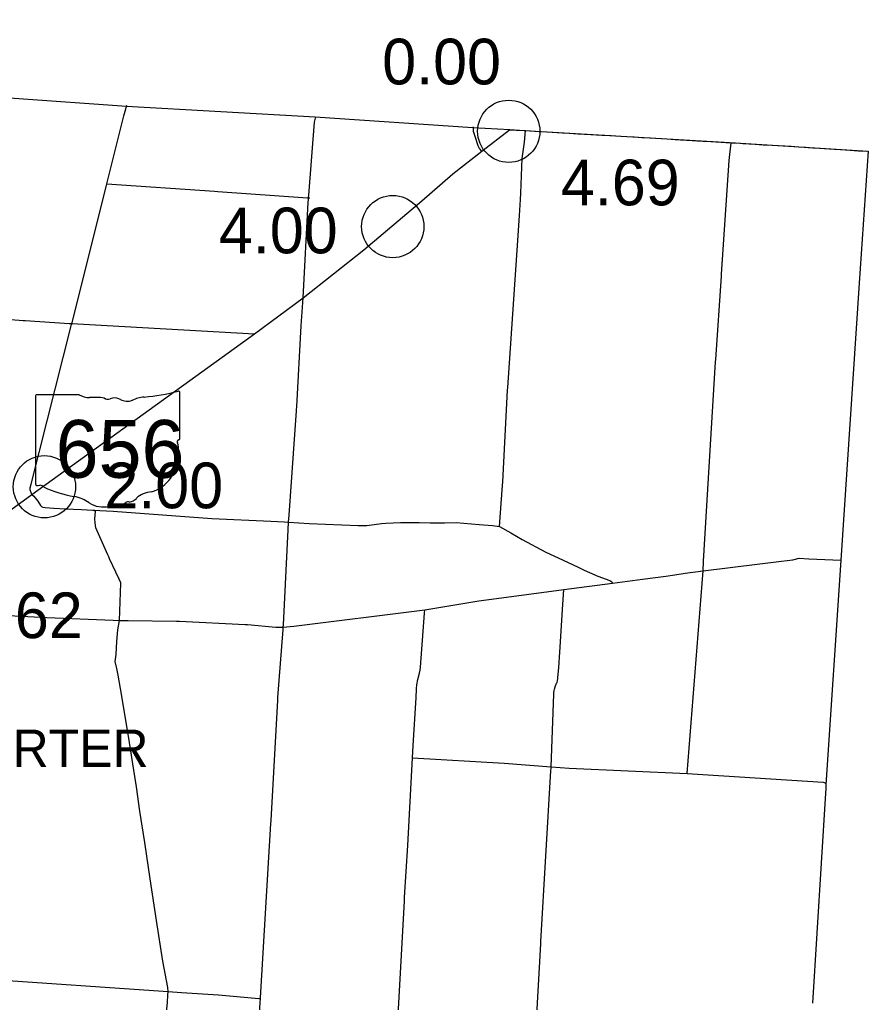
# Model space of a CAD drawing. Extents: x 1597222 to 1925846, y 496284 to 911751.
# Drawn here: x 1879776 to 1900207, y 835395 to 859080 of the extents above; entities that cross this region are included whole.
import ezdxf

# ---------------------------------------------------------------- set-up
doc = ezdxf.new("R2010")
doc.units = 0
for name, color, linetype in [('Default', 7, 'Continuous'), ('GM_X_County', 7, 'Continuous'), ('GM_X_County_Road', 7, 'Continuous'), ('GM_X_State_Route', 7, 'Continuous'), ('GM_X_State_Shield', 7, 'Continuous'), ('GM_X_Township_Road', 7, 'Continuous'), ('GM_X_Township_Text', 7, 'Continuous')]:
    doc.layers.add(name, color=color, linetype=linetype)

msp = doc.modelspace()

# ---------------------------------------------------------------- linework, layer by layer
at = {"layer": 'Default'}
for centre in [(1891564, 856389), (1891564, 856389), (1888769, 854093), (1880372, 847822)]:
    msp.add_circle(centre, 750, dxfattribs=at)
at = {"layer": 'GM_X_County'}
msp.add_lwpolyline([(1850615, 859080), (1861827, 858324), (1863977, 858188), (1869100, 857855), (1873671, 857558), (1876143, 857428), (1879641, 857188), (1882352, 856998), (1886895, 856734), (1890695, 856480), (1891588, 856432), (1891937, 856405), (1896895, 856116), (1900228, 855908), (1900008, 852727), (1899571, 846055), (1899210, 840637), (1899208, 840537), (1899202, 840435), (1898887, 835373)], dxfattribs=at)
at = {"layer": 'GM_X_County_Road'}
for points in [[(1886129, 844439), (1886132, 844491), (1886249, 846785), (1886257, 846969), (1886270, 847136), (1886449, 849651), (1886451, 849675), (1886456, 849754), (1886558, 851700), (1886613, 852377)], [(1879351, 844730), (1880430, 844669), (1882026, 844608), (1882181, 844601), (1882392, 844602), (1883554, 844583), (1883632, 844581), (1885215, 844502), (1885270, 844499), (1885954, 844440), (1886129, 844439), (1886387, 844458), (1889478, 844848), (1889539, 844855), (1890840, 845073), (1892109, 845243), (1892893, 845346), (1894066, 845501), (1894790, 845594), (1895349, 845664), (1895569, 845695), (1895814, 845736), (1896247, 845793), (1896967, 845887), (1898141, 846028), (1898411, 846062), (1898560, 846100), (1898798, 846088), (1899571, 846055)], [(1888604, 829939), (1888609, 830001), (1888760, 832637), (1888800, 833137), (1888812, 833505), (1889049, 837835), (1889053, 837918), (1889133, 839176), (1889247, 841285), (1889264, 841582), (1889332, 842735), (1889339, 842955), (1889347, 843044), (1889371, 843177), (1889414, 843329), (1889428, 843400), (1889436, 843472), (1889534, 844778), (1889539, 844855)], [(1883352, 835653), (1883345, 835749), (1883225, 836391), (1883075, 837371), (1882925, 838372), (1882793, 839248), (1882676, 839999), (1882590, 840590), (1882528, 840993), (1882422, 841658), (1882235, 842776), (1882147, 843282), (1882115, 843443), (1882081, 843608), (1882104, 843778), (1882120, 844088), (1882142, 844371), (1882181, 844601)], [(1883240, 831567), (1883121, 831886), (1883110, 832097), (1883136, 832477), (1883174, 833194), (1883211, 833953), (1883259, 834488), (1883303, 835001), (1883338, 835393), (1883351, 835566), (1883352, 835653)]]:
    msp.add_lwpolyline(points, dxfattribs=at)
at = {"layer": 'GM_X_State_Route'}
msp.add_lwpolyline([(1877908, 846019), (1878069, 846144), (1878991, 846854), (1880073, 847637), (1885437, 851504), (1886613, 852377), (1888074, 853536), (1889468, 854711), (1890217, 855366), (1890913, 855912), (1891583, 856425)], dxfattribs=at)
at = {"layer": 'GM_X_State_Shield'}
for p, q in [((1883638, 848987), (1883638, 850092)), ((1883638, 848987), (1883638, 850092)), ((1880157, 850003), (1880157, 847890)), ((1880157, 850003), (1880157, 847890)), ((1881211, 850040), (1880192, 850040)), ((1881211, 850040), (1880192, 850040)), ((1883637, 848987), (1883638, 848987)), ((1883637, 848987), (1883638, 848987))]:
    msp.add_line(p, q, dxfattribs=at)
for centre, major_axis, start_param, end_param in [((1882398, 852921), (3691, 0), 4.814394, 5.042369), ((1882398, 852921), (3691, 0), 4.814394, 5.042369), ((1883599, 850097), (38.7, 0), 6.141152, 7.989035), ((1883599, 850097), (38.7, 0), 6.141152, 7.989035), ((1880197, 850008), (40.3, 0), 1.712693, 3.28349), ((1880197, 850008), (40.3, 0), 1.712693, 3.28349), ((1881453, 850285), (391, 0), 4.042523, 4.731795), ((1881453, 850285), (391, 0), 4.042523, 4.731795), ((1881583, 848853), (1404, 0), 1.404758, 1.657858), ((1881583, 848853), (1404, 0), 1.404758, 1.657858), ((1881902, 850019), (113, 0), 3.836095, 5.185415), ((1881902, 850019), (113, 0), 3.836095, 5.185415), ((1882068, 849775), (235, 0), 0.950623, 2.079405), ((1882068, 849775), (235, 0), 0.950623, 2.079405), ((1882370, 850110), (282, 0), 4.081561, 5.145723), ((1882370, 850110), (282, 0), 4.081561, 5.145723), ((1882869, 849394), (743, 0), 1.699011, 2.107814), ((1882869, 849394), (743, 0), 1.699011, 2.107814), ((1883629, 848905), (60, 0), 1.883978, 3.671073), ((1883629, 848905), (60, 0), 1.883978, 3.671073), ((1883596, 848982), (41.5, 0), 5.05454, 6.418171), ((1883596, 848982), (41.5, 0), 5.05454, 6.418171), ((1883776, 848524), (262, 0), 2.387724, 3.262537), ((1883776, 848524), (262, 0), 2.387724, 3.262537), ((1883247, 848766), (360, 0), 5.934695, 6.695948), ((1883247, 848766), (360, 0), 5.934695, 6.695948), ((1882605, 848383), (923, 0), 5.101752, 6.440018), ((1882605, 848383), (923, 0), 5.101752, 6.440018), ((1880197, 847885), (40.7, 0), 3.00124, 4.508301), ((1880197, 847885), (40.7, 0), 3.00124, 4.508301), ((1880204, 848102), (310, 0), 4.665946, 4.897461), ((1880204, 848102), (310, 0), 4.665946, 4.897461), ((1880267, 847768), (112, 0), 0.519207, 1.627899), ((1880267, 847768), (112, 0), 0.519207, 1.627899), ((1881680, 849667), (2665, 0), 4.195997, 4.488961), ((1881680, 849667), (2665, 0), 4.195997, 4.488961), ((1880886, 846941), (834, 0), 0.823519, 1.323587), ((1880886, 846941), (834, 0), 0.823519, 1.323587), ((1882353, 847685), (298, 0), 4.937069, 5.64225), ((1882353, 847685), (298, 0), 4.937069, 5.64225), ((1882994, 847297), (506, 0), 1.647645, 2.488434), ((1882994, 847297), (506, 0), 1.647645, 2.488434), ((1881788, 847758), (529, 0), 4.026481, 4.996735), ((1881788, 847758), (529, 0), 4.026481, 4.996735), ((1882093, 847027), (435, 0), 1.495662, 1.94098), ((1882093, 847027), (435, 0), 1.495662, 1.94098), ((1882132, 847599), (282, 0), 4.691044, 5.507374), ((1882132, 847599), (282, 0), 4.691044, 5.507374), ((1882387, 847395), (79.4, 0), 1.147584, 2.315152), ((1882387, 847395), (79.4, 0), 1.147584, 2.315152)]:
    msp.add_ellipse(centre, major_axis=major_axis, ratio=0.8, start_param=start_param, end_param=end_param, dxfattribs=at)
at = {"layer": 'GM_X_Township_Road'}
for points in [[(1881030, 851742), (1881033, 851753), (1881038, 851772), (1881876, 855126), (1882288, 856762), (1882322, 856876), (1882360, 857020)], [(1886743, 854850), (1886885, 856612), (1886918, 856737)], [(1890913, 855912), (1890862, 855972), (1890828, 856035), (1890756, 856263), (1890718, 856382), (1890717, 856500)], [(1891583, 856425), (1891639, 856423), (1891746, 856417), (1891965, 856405)], [(1891854, 854895), (1891886, 855736), (1891944, 856127), (1891965, 856405)], [(1891965, 856405), (1892090, 856398), (1892301, 856385), (1892481, 856374), (1892856, 856351), (1893019, 856342), (1893232, 856329), (1893543, 856312), (1893805, 856297), (1893879, 856293), (1894034, 856284), (1894263, 856272), (1894410, 856264), (1894590, 856253), (1894770, 856241), (1894983, 856228), (1895376, 856205), (1895572, 856194), (1895703, 856186), (1895981, 856169), (1896095, 856161), (1896177, 856156), (1896242, 856153), (1896308, 856149), (1896553, 856136), (1896684, 856128), (1896799, 856122), (1896913, 856115), (1896923, 856115)], [(1896693, 852936), (1896693, 852946), (1896876, 855684), (1896923, 856115)], [(1896923, 856115), (1897028, 856108), (1897142, 856101), (1897208, 856097), (1897503, 856079), (1897601, 856072), (1897699, 856066), (1897780, 856061), (1897911, 856054), (1898222, 856035), (1898370, 856027), (1898550, 856015), (1898713, 856004), (1898778, 856000), (1898893, 855993), (1899057, 855983), (1899416, 855960), (1899563, 855950), (1899678, 855942), (1899792, 855935), (1899988, 855922), (1900186, 855910)], [(1881876, 855126), (1884475, 854944), (1884555, 854939), (1886714, 854786), (1886737, 854784), (1886771, 854782)], [(1886613, 852377), (1886732, 854673), (1886735, 854748), (1886736, 854770), (1886737, 854784), (1886738, 854791), (1886743, 854850)], [(1891340, 846864), (1891414, 847853), (1891419, 847939), (1891537, 850153), (1891540, 850214), (1891785, 853757), (1891824, 854360), (1891848, 854742), (1891854, 854895)], [(1896247, 845793), (1896262, 846026), (1896550, 850831), (1896553, 850892), (1896690, 852894), (1896692, 852927), (1896693, 852936)], [(1878551, 851936), (1879863, 851829)], [(1879863, 851829), (1879912, 851825), (1880967, 851757)], [(1880073, 847637), (1880028, 847749), (1880030, 847793), (1880052, 847886), (1881020, 851698), (1881027, 851730), (1881030, 851742)], [(1880967, 851757), (1881014, 851754), (1881019, 851754), (1881033, 851753), (1885437, 851504)], [(1880073, 847637), (1880119, 847597), (1880215, 847475), (1880282, 847373), (1880306, 847346), (1880336, 847332), (1880393, 847320), (1880601, 847305), (1880879, 847291), (1881267, 847277), (1881536, 847259), (1881580, 847257), (1881708, 847250), (1882026, 847230), (1884406, 847060), (1885829, 846989), (1886154, 846974), (1886257, 846969), (1886753, 846940), (1887931, 846886), (1888141, 846889), (1888497, 846936), (1888601, 846948), (1888952, 846957), (1889403, 846957), (1889669, 846954), (1890015, 846956), (1890296, 846958), (1890853, 846915), (1891169, 846885), (1891340, 846864)], [(1882181, 844601), (1882218, 845500), (1882218, 845505), (1882178, 845591), (1881944, 846088), (1881925, 846129), (1881900, 846178), (1881613, 846828), (1881595, 846950), (1881589, 847049), (1881601, 847222), (1881580, 847257)], [(1891340, 846864), (1891616, 846711), (1891890, 846553), (1892461, 846246), (1892758, 846106), (1893234, 845882), (1893382, 845812), (1893507, 845752), (1893710, 845669), (1893997, 845564), (1894023, 845549), (1894046, 845529), (1894066, 845501)], [(1895863, 840910), (1896247, 845793)], [(1892122, 832957), (1892339, 836806), (1892341, 836860), (1892582, 840972), (1892585, 841036), (1892586, 841074), (1892651, 842825), (1892652, 842854), (1892658, 842912), (1892664, 842941), (1892680, 842997), (1892719, 843085), (1892728, 843106), (1892742, 843149), (1892749, 843194), (1892750, 843216), (1892770, 843468), (1892794, 843834), (1892869, 844984), (1892893, 845346)], [(1885446, 833427), (1885462, 833535), (1885473, 833796), (1885574, 835394), (1885580, 835487), (1885580, 835490), (1885581, 835505), (1885831, 839707), (1885835, 839776), (1885999, 842676), (1886002, 842745), (1886125, 844378), (1886129, 844439)], [(1889247, 841285), (1891451, 841156), (1892586, 841074), (1893022, 841042), (1895863, 840910), (1899143, 840698), (1899170, 840695), (1899188, 840685), (1899198, 840677), (1899202, 840668), (1899210, 840637), (1899208, 840537)], [(1878279, 835990), (1878360, 835995), (1878441, 835994), (1878907, 835961), (1883352, 835653)], [(1883352, 835653), (1883676, 835633), (1884568, 835572), (1885540, 835488), (1885580, 835487), (1885592, 835487)]]:
    msp.add_lwpolyline(points, dxfattribs=at)

# ---------------------------------------------------------------- texts
at = {"layer": 'Default'}
for s, p in [('0.00', (1888514, 857520)), ('4.69', (1892821, 854605)), ('4.00', (1884578, 853449)), ('2.00', (1881818, 847304)), ('13.62', (1877615, 844173))]:
    msp.add_text(s, height=1100, dxfattribs=at).set_placement(p)
at = {"layer": 'GM_X_State_Shield'}
msp.add_text('656', height=1392.2, dxfattribs=at).set_placement((1880642, 848039))
msp.add_text('656', height=1392.2, dxfattribs=at).set_placement((1880642, 848039))
at = {"layer": 'GM_X_Township_Text'}
msp.add_text('PORTER', height=900, rotation=0, dxfattribs=at).set_placement((1877867, 841070))

doc.saveas('drawing.dxf')
